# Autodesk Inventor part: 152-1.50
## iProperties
Created: 2007-06
Part Number: 152-1.50
Document SubType Name: Modeling
Designer: btaylor
Density: 1 g/cm^3
Author: btaylor
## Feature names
1. Sweep1
2. Extrusion1
3. Extrusion2
4. Fillet1
5. Fillet2
6. Extrusion3
7. Chamfer1
8. Fillet3
9. Chamfer2
10. Sweep2
11. Fillet4
12. Fillet5
13. Fillet6
